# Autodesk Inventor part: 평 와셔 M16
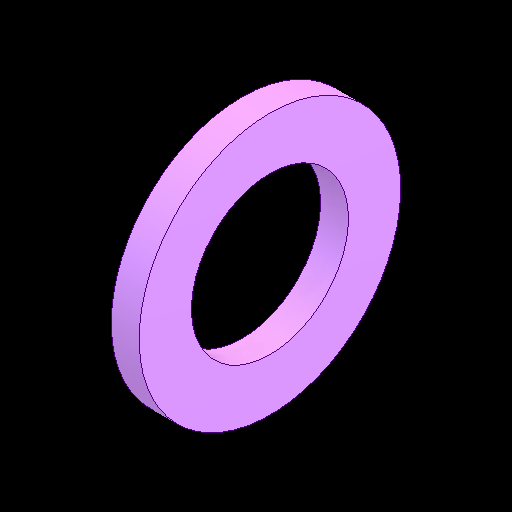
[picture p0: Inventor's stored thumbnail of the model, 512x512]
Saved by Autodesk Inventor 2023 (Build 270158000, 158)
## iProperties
Created: 2025-01
Part Number: 평 와셔 M16
Material: 강철, 연강
Description: 평면 와셔
Document SubType Name: Modeling
Designer: 강의실01
Density: 7.85 g/cm^3
Appearance: 기본값
Author: jhkim
Sending System: Autodesk Inventor 2025
Preprocessor: ST-DEVELOPER v20
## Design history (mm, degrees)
feature "Solid1"
node "솔리드1"
